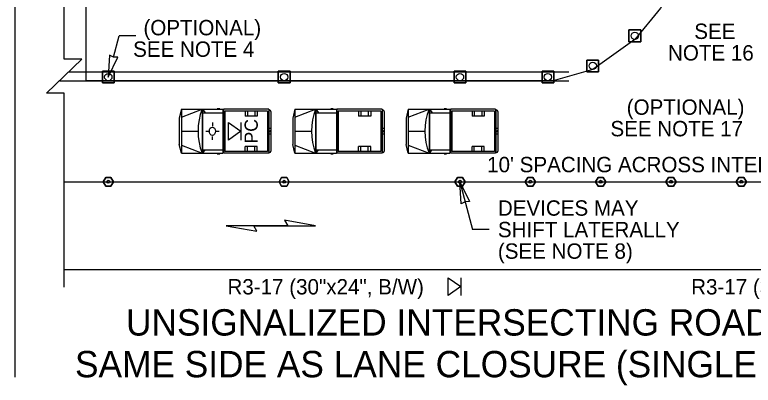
# Model space of a CAD drawing. Extents: x 99999.1 to 100095.7, y 99995 to 100010.7.
# Drawn here: x 100065.25 to 100068.61, y 100001.65 to 100003.336 of the extents above; entities that cross this region are included whole.
import ezdxf

# ---------------------------------------------------------------- set-up
doc = ezdxf.new("R2010")
doc.units = 0
for name, color, linetype in [('RD_ED_ShoulderPavedEdge', 7, 'Continuous'), ('RD_MK_LineDblYellowCenter', 7, 'Continuous'), ('RD_MK_LineEdgeWhite', 7, 'Continuous'), ('SH_DE_DetailHeading2Text', 7, 'Continuous'), ('TR_WZ_MotoristVehicle', 7, 'Continuous'), ('TR_WZ_PortableSignMountBlk-Wht', 7, 'Continuous'), ('TR_WZ_TrafficCone', 7, 'Continuous'), ('TR_WZ_TubularMarker', 7, 'Continuous'), ('TR_WZ_WorkZoneDetails', 7, 'Continuous'), ('TR_WZ_WorkZoneTextCurrent', 7, 'Continuous')]:
    doc.layers.add(name, color=color, linetype=linetype)

msp = doc.modelspace()

# ---------------------------------------------------------------- linework, layer by layer
at = {"layer": 'RD_ED_ShoulderPavedEdge'}
msp.add_line((100065.475, 100002.1759), (100070.275, 100002.1759), dxfattribs=at)
at = {"layer": 'RD_MK_LineDblYellowCenter'}
for p, q in [((100065.4957, 100003.0759), (100067.7712, 100003.0759)), ((100065.4543, 100003.0359), (100067.7712, 100003.0359))]:
    msp.add_line(p, q, dxfattribs=at)
at = {"layer": 'RD_MK_LineEdgeWhite'}
msp.add_line((100065.475, 100002.5759), (100070.275, 100002.5759), dxfattribs=at)
at = {"layer": 'TR_WZ_MotoristVehicle'}
for p, q in [((100066.008, 100002.9059), (100065.9987, 100002.8655)), ((100066.008, 100002.9059), (100066.008, 100002.7059)), ((100066.008, 100002.9059), (100066.1969, 100002.9059)), ((100066.008, 100002.8693), (100066.1025, 100002.9059)), ((100066.1025, 100002.9059), (100066.1025, 100002.7059)), ((100066.1042, 100002.9059), (100066.1042, 100002.7059)), ((100066.1042, 100002.9059), (100066.1162, 100002.8904)), ((100066.1042, 100002.8904), (100066.1969, 100002.8904)), ((100066.1712, 100002.9087), (100066.1825, 100002.9087)), ((100066.1969, 100002.9059), (100066.1969, 100002.7059)), ((100066.4054, 100002.9059), (100066.1997, 100002.9059)), ((100066.1997, 100002.9059), (100066.1997, 100002.7059)), ((100066.3995, 100002.8979), (100066.2055, 100002.8979)), ((100066.2055, 100002.8979), (100066.2055, 100002.7139)), ((100066.2982, 100002.8979), (100066.2982, 100002.8749)), ((100066.3082, 100002.8979), (100066.3082, 100002.8749)), ((100066.3422, 100002.8979), (100066.3422, 100002.8749)), ((100066.3532, 100002.8979), (100066.3532, 100002.8749)), ((100066.3995, 100002.8979), (100066.3995, 100002.7139)), ((100066.4054, 100002.9059), (100066.4054, 100002.7059)), ((100066.4105, 100002.9026), (100066.4061, 100002.9026)), ((100066.4061, 100002.9026), (100066.4061, 100002.7092)), ((100066.415, 100002.8965), (100066.415, 100002.7153)), ((100066.5243, 100002.9059), (100066.515, 100002.8655)), ((100066.5243, 100002.9059), (100066.5243, 100002.7059)), ((100066.5243, 100002.9059), (100066.7132, 100002.9059)), ((100066.5243, 100002.8693), (100066.6187, 100002.9059)), ((100066.6187, 100002.9059), (100066.6187, 100002.7059)), ((100066.6204, 100002.9059), (100066.6204, 100002.7059)), ((100066.6204, 100002.9059), (100066.6325, 100002.8904)), ((100066.6204, 100002.8904), (100066.7132, 100002.8904)), ((100066.6874, 100002.9087), (100066.6987, 100002.9087)), ((100066.7132, 100002.9059), (100066.7132, 100002.7059)), ((100066.9216, 100002.9059), (100066.7159, 100002.9059)), ((100066.7159, 100002.9059), (100066.7159, 100002.7059)), ((100066.9158, 100002.8979), (100066.7218, 100002.8979)), ((100066.7218, 100002.8979), (100066.7218, 100002.7139)), ((100066.8145, 100002.8979), (100066.8145, 100002.8749)), ((100066.8244, 100002.8979), (100066.8244, 100002.8749)), ((100066.8585, 100002.8979), (100066.8585, 100002.8749)), ((100066.8694, 100002.8979), (100066.8694, 100002.8749)), ((100066.9158, 100002.8979), (100066.9158, 100002.7139)), ((100066.9216, 100002.9059), (100066.9216, 100002.7059)), ((100066.9268, 100002.9026), (100066.9223, 100002.9026)), ((100066.9223, 100002.9026), (100066.9223, 100002.7092)), ((100066.9313, 100002.8965), (100066.9313, 100002.7153)), ((100067.0405, 100002.9059), (100067.0313, 100002.8655)), ((100067.0405, 100002.9059), (100067.0405, 100002.7059)), ((100067.0405, 100002.9059), (100067.2294, 100002.9059)), ((100067.0405, 100002.8693), (100067.135, 100002.9059)), ((100067.135, 100002.9059), (100067.135, 100002.7059)), ((100067.1367, 100002.9059), (100067.1367, 100002.7059)), ((100067.1367, 100002.9059), (100067.1487, 100002.8904)), ((100067.1367, 100002.8904), (100067.2294, 100002.8904)), ((100067.2037, 100002.9087), (100067.215, 100002.9087)), ((100067.2294, 100002.9059), (100067.2294, 100002.7059)), ((100067.4379, 100002.9059), (100067.2322, 100002.9059)), ((100067.2322, 100002.9059), (100067.2322, 100002.7059)), ((100067.4321, 100002.8979), (100067.238, 100002.8979)), ((100067.238, 100002.8979), (100067.238, 100002.7139)), ((100067.3308, 100002.8979), (100067.3308, 100002.8749)), ((100067.3407, 100002.8979), (100067.3407, 100002.8749)), ((100067.3747, 100002.8979), (100067.3747, 100002.8749)), ((100067.3857, 100002.8979), (100067.3857, 100002.8749)), ((100067.4321, 100002.8979), (100067.4321, 100002.7139)), ((100067.4379, 100002.9059), (100067.4379, 100002.7059)), ((100067.4431, 100002.9026), (100067.4386, 100002.9026)), ((100067.4386, 100002.9026), (100067.4386, 100002.7092)), ((100067.4475, 100002.8965), (100067.4475, 100002.7153)), ((100065.9987, 100002.8655), (100065.9987, 100002.7463)), ((100066.3532, 100002.8749), (100066.2982, 100002.8749)), ((100066.515, 100002.8655), (100066.515, 100002.7463)), ((100066.8694, 100002.8749), (100066.8145, 100002.8749)), ((100067.0313, 100002.8655), (100067.0313, 100002.7463)), ((100067.3857, 100002.8749), (100067.3308, 100002.8749)), ((100066.1495, 100002.8455), (100066.1495, 100002.8294)), ((100066.415, 100002.82), (100066.4061, 100002.8162)), ((100066.9313, 100002.82), (100066.9223, 100002.8162)), ((100067.4475, 100002.82), (100067.4386, 100002.8162)), ((100066.008, 100002.8059), (100066.0839, 100002.8059)), ((100066.1194, 100002.806), (100066.132, 100002.806)), ((100066.1636, 100002.8056), (100066.1636, 100002.8056)), ((100066.1804, 100002.8051), (100066.1655, 100002.8055)), ((100066.415, 100002.7918), (100066.4061, 100002.7956)), ((100066.4126, 100002.8059), (100066.4085, 100002.8059)), ((100066.4105, 100002.8087), (100066.4105, 100002.8031)), ((100066.5243, 100002.8059), (100066.6002, 100002.8059)), ((100066.9313, 100002.7918), (100066.9223, 100002.7956)), ((100066.9289, 100002.8059), (100066.9247, 100002.8059)), ((100066.9268, 100002.8087), (100066.9268, 100002.8031)), ((100067.0405, 100002.8059), (100067.1164, 100002.8059)), ((100067.4475, 100002.7918), (100067.4386, 100002.7956)), ((100067.4451, 100002.8059), (100067.441, 100002.8059)), ((100067.4431, 100002.8087), (100067.4431, 100002.8031)), ((100066.1502, 100002.7674), (100066.1499, 100002.7825)), ((100066.008, 100002.7059), (100065.9987, 100002.7463)), ((100066.008, 100002.7425), (100066.1025, 100002.7059)), ((100066.1042, 100002.7214), (100066.1969, 100002.7214)), ((100066.1141, 100002.7214), (100066.1042, 100002.7059)), ((100066.2982, 100002.7139), (100066.2982, 100002.7369)), ((100066.3532, 100002.7369), (100066.2982, 100002.7369)), ((100066.3082, 100002.7139), (100066.3082, 100002.7369)), ((100066.3422, 100002.7139), (100066.3422, 100002.7369)), ((100066.3532, 100002.7139), (100066.3532, 100002.7369)), ((100066.5243, 100002.7059), (100066.515, 100002.7463)), ((100066.5243, 100002.7425), (100066.6187, 100002.7059)), ((100066.6204, 100002.7214), (100066.7132, 100002.7214)), ((100066.6304, 100002.7214), (100066.6204, 100002.7059)), ((100066.8145, 100002.7139), (100066.8145, 100002.7369)), ((100066.8694, 100002.7369), (100066.8145, 100002.7369)), ((100066.8244, 100002.7139), (100066.8244, 100002.7369)), ((100066.8585, 100002.7139), (100066.8585, 100002.7369)), ((100066.8694, 100002.7139), (100066.8694, 100002.7369)), ((100067.0405, 100002.7059), (100067.0313, 100002.7463)), ((100067.0405, 100002.7425), (100067.135, 100002.7059)), ((100067.1367, 100002.7214), (100067.2294, 100002.7214)), ((100067.1467, 100002.7214), (100067.1367, 100002.7059)), ((100067.3308, 100002.7139), (100067.3308, 100002.7369)), ((100067.3857, 100002.7369), (100067.3308, 100002.7369)), ((100067.3407, 100002.7139), (100067.3407, 100002.7369)), ((100067.3747, 100002.7139), (100067.3747, 100002.7369)), ((100067.3857, 100002.7139), (100067.3857, 100002.7369)), ((100066.008, 100002.7059), (100066.1969, 100002.7059)), ((100066.1712, 100002.7031), (100066.1825, 100002.7031)), ((100066.4054, 100002.7059), (100066.1997, 100002.7059)), ((100066.3995, 100002.7139), (100066.2055, 100002.7139)), ((100066.4105, 100002.7092), (100066.4061, 100002.7092)), ((100066.5243, 100002.7059), (100066.7132, 100002.7059)), ((100066.6874, 100002.7031), (100066.6987, 100002.7031)), ((100066.9216, 100002.7059), (100066.7159, 100002.7059)), ((100066.9158, 100002.7139), (100066.7218, 100002.7139)), ((100066.9268, 100002.7092), (100066.9223, 100002.7092)), ((100067.0405, 100002.7059), (100067.2294, 100002.7059)), ((100067.2037, 100002.7031), (100067.215, 100002.7031)), ((100067.4379, 100002.7059), (100067.2322, 100002.7059)), ((100067.4321, 100002.7139), (100067.238, 100002.7139)), ((100067.4431, 100002.7092), (100067.4386, 100002.7092))]:
    msp.add_line(p, q, dxfattribs=at)
for centre, major_axis, start_param, end_param in [((100066.2374, 100002.8059), (0, -0.2099), 4.215667, 5.208926), ((100066.4105, 100002.8965), (0, 0.0061), 4.712389, 6.283185), ((100066.7537, 100002.8059), (0, -0.2099), 4.215667, 5.208926), ((100066.9268, 100002.8965), (0, 0.0061), 4.712389, 6.283185), ((100067.27, 100002.8059), (0, -0.2099), 4.215667, 5.208926), ((100067.4431, 100002.8965), (0, 0.0061), 4.712389, 6.283185), ((100066.4105, 100002.7153), (0, -0.0061), 0, 1.570796), ((100066.9268, 100002.7153), (0, -0.0061), 0, 1.570796), ((100067.4431, 100002.7153), (0, -0.0061), 0, 1.570796)]:
    msp.add_ellipse(centre, major_axis=major_axis, ratio=0.73155, start_param=start_param, end_param=end_param, dxfattribs=at)
for centre, major_axis in [((100066.1495, 100002.8059), (0, 0.0193)), ((100066.4105, 100002.8059), (0, 0.00282)), ((100066.9268, 100002.8059), (0, 0.00282)), ((100067.4431, 100002.8059), (0, 0.00282))]:
    msp.add_ellipse(centre, major_axis=major_axis, ratio=0.73155, dxfattribs=at)
at = {"layer": 'TR_WZ_PortableSignMountBlk-Wht'}
for p, q in [((100066.2793, 100002.8458), (100066.2793, 100002.7658)), ((100067.279, 100002.1389), (100067.279, 100002.0589))]:
    msp.add_line(p, q, dxfattribs=at)
for points in [[(100066.2793, 100002.8059), (100066.2219, 100002.7658), (100066.2219, 100002.8458)], [(100067.279, 100002.0989), (100067.2215, 100002.0589), (100067.2215, 100002.1389)]]:
    msp.add_lwpolyline(points, close=True, dxfattribs=at)
at = {"layer": 'TR_WZ_TrafficCone'}
for points in [[(100068.0447, 100003.267), (100068.0981, 100003.267), (100068.0981, 100003.2136), (100068.0447, 100003.2136), (100068.0447, 100003.267)], [(100068.0447, 100003.2136), (100068.0981, 100003.2136), (100068.0981, 100003.267), (100068.0447, 100003.267), (100068.0447, 100003.2136)], [(100067.853, 100003.1302), (100067.9064, 100003.1302), (100067.9064, 100003.0768), (100067.853, 100003.0768), (100067.853, 100003.1302)], [(100067.853, 100003.0768), (100067.9064, 100003.0768), (100067.9064, 100003.1302), (100067.853, 100003.1302), (100067.853, 100003.0768)], [(100065.649, 100003.0792), (100065.7024, 100003.0792), (100065.7024, 100003.0259), (100065.649, 100003.0259), (100065.649, 100003.0792)], [(100065.649, 100003.0259), (100065.7024, 100003.0259), (100065.7024, 100003.0792), (100065.649, 100003.0792), (100065.649, 100003.0259)], [(100066.449, 100003.0792), (100066.5024, 100003.0792), (100066.5024, 100003.0259), (100066.449, 100003.0259), (100066.449, 100003.0792)], [(100066.449, 100003.0259), (100066.5024, 100003.0259), (100066.5024, 100003.0792), (100066.449, 100003.0792), (100066.449, 100003.0259)], [(100067.249, 100003.0792), (100067.3024, 100003.0792), (100067.3024, 100003.0259), (100067.249, 100003.0259), (100067.249, 100003.0792)], [(100067.249, 100003.0259), (100067.3024, 100003.0259), (100067.3024, 100003.0792), (100067.249, 100003.0792), (100067.249, 100003.0259)], [(100067.649, 100003.0792), (100067.7024, 100003.0792), (100067.7024, 100003.0259), (100067.649, 100003.0259), (100067.649, 100003.0792)], [(100067.649, 100003.0259), (100067.7024, 100003.0259), (100067.7024, 100003.0792), (100067.649, 100003.0792), (100067.649, 100003.0259)]]:
    msp.add_lwpolyline(points, dxfattribs=at)
for centre in [(100068.0714, 100003.2403), (100067.8797, 100003.1035), (100065.6757, 100003.0526), (100066.4757, 100003.0526), (100067.2757, 100003.0526), (100067.6757, 100003.0526)]:
    msp.add_circle(centre, 0.0167, dxfattribs=at)
at = {"layer": 'TR_WZ_TubularMarker'}
for points in [[(100065.6526, 100002.5759), (100065.6641, 100002.5959), (100065.6872, 100002.5959), (100065.6988, 100002.5759), (100065.6872, 100002.5559), (100065.6641, 100002.5559)], [(100066.4526, 100002.5759), (100066.4641, 100002.5959), (100066.4872, 100002.5959), (100066.4988, 100002.5759), (100066.4872, 100002.5559), (100066.4641, 100002.5559)], [(100067.2526, 100002.5759), (100067.2641, 100002.5959), (100067.2872, 100002.5959), (100067.2988, 100002.5759), (100067.2872, 100002.5559), (100067.2641, 100002.5559)], [(100067.5726, 100002.5759), (100067.5841, 100002.5959), (100067.6072, 100002.5959), (100067.6188, 100002.5759), (100067.6072, 100002.5559), (100067.5841, 100002.5559)], [(100067.8926, 100002.5759), (100067.9041, 100002.5959), (100067.9272, 100002.5959), (100067.9388, 100002.5759), (100067.9272, 100002.5559), (100067.9041, 100002.5559)], [(100068.2126, 100002.5759), (100068.2241, 100002.5959), (100068.2472, 100002.5959), (100068.2588, 100002.5759), (100068.2472, 100002.5559), (100068.2241, 100002.5559)], [(100068.5326, 100002.5759), (100068.5441, 100002.5959), (100068.5672, 100002.5959), (100068.5788, 100002.5759), (100068.5672, 100002.5559), (100068.5441, 100002.5559)]]:
    msp.add_lwpolyline(points, close=True, dxfattribs=at)
for points in [[(100065.6641, 100002.5559), (100065.6872, 100002.5559), (100065.6988, 100002.5759), (100065.6872, 100002.5959), (100065.6641, 100002.5959), (100065.6526, 100002.5759), (100065.6641, 100002.5559)], [(100066.4641, 100002.5559), (100066.4872, 100002.5559), (100066.4988, 100002.5759), (100066.4872, 100002.5959), (100066.4641, 100002.5959), (100066.4526, 100002.5759), (100066.4641, 100002.5559)], [(100067.2641, 100002.5559), (100067.2872, 100002.5559), (100067.2988, 100002.5759), (100067.2872, 100002.5959), (100067.2641, 100002.5959), (100067.2526, 100002.5759), (100067.2641, 100002.5559)], [(100067.5841, 100002.5559), (100067.6072, 100002.5559), (100067.6188, 100002.5759), (100067.6072, 100002.5959), (100067.5841, 100002.5959), (100067.5726, 100002.5759), (100067.5841, 100002.5559)], [(100067.9041, 100002.5559), (100067.9272, 100002.5559), (100067.9388, 100002.5759), (100067.9272, 100002.5959), (100067.9041, 100002.5959), (100067.8926, 100002.5759), (100067.9041, 100002.5559)], [(100068.2241, 100002.5559), (100068.2472, 100002.5559), (100068.2588, 100002.5759), (100068.2472, 100002.5959), (100068.2241, 100002.5959), (100068.2126, 100002.5759), (100068.2241, 100002.5559)], [(100068.5441, 100002.5559), (100068.5672, 100002.5559), (100068.5788, 100002.5759), (100068.5672, 100002.5959), (100068.5441, 100002.5959), (100068.5326, 100002.5759), (100068.5441, 100002.5559)]]:
    msp.add_lwpolyline(points, dxfattribs=at)
for centre in [(100065.6757, 100002.5759), (100066.4757, 100002.5759), (100067.2757, 100002.5759), (100067.5957, 100002.5759), (100067.9157, 100002.5759), (100068.2357, 100002.5759), (100068.5557, 100002.5759)]:
    msp.add_circle(centre, 0.00667, dxfattribs=at)
at = {"layer": 'TR_WZ_WorkZoneDetails'}
for p, q in [((100065.25, 100010.275), (100065.25, 100001.6859)), ((100065.6993, 100003.1433), (100065.7245, 100003.2406)), ((100065.8007, 100003.2406), (100065.7245, 100003.2406)), ((100067.2757, 100002.5759), (100067.3321, 100002.3584)), ((100066.4922, 100002.3759), (100066.3378, 100002.3759)), ((100066.3378, 100002.3759), (100066.4922, 100002.3759)), ((100067.4083, 100002.3584), (100067.3321, 100002.3584))]:
    msp.add_line(p, q, dxfattribs=at)
msp.add_lwpolyline([(100065.475, 100002.0959), (100065.475, 100002.9785), (100065.395, 100002.9785), (100065.555, 100003.1333), (100065.475, 100003.1333), (100065.475, 100004.0159)], dxfattribs=at)
for points in [[(100068.3383, 100003.9359), (100068.3383, 100003.7126), (100068.264, 100003.5159), (100068.1883, 100003.3659), (100068.1883, 100003.3659), (100068.1883, 100003.3659), (100068.0714, 100003.2236), (100068.0714, 100003.2236), (100068.0714, 100003.2236), (100067.8797, 100003.0868), (100067.699, 100003.0359), (100066.499, 100003.0359), (100065.699, 100003.0359), (100065.575, 100003.0359), (100065.575, 100003.9359)], [(100065.6757, 100003.0526), (100065.719, 100003.1429), (100065.6992, 100003.1433), (100065.6817, 100003.1525)], [(100067.2757, 100002.5759), (100067.319, 100002.4856), (100067.2992, 100002.4852), (100067.2816, 100002.4759)], [(100066.6179, 100002.3759), (100066.4779, 100002.4006), (100066.4922, 100002.3759)], [(100066.2121, 100002.3759), (100066.3521, 100002.3512), (100066.3378, 100002.3759)]]:
    msp.add_lwpolyline(points, close=True, dxfattribs=at)

# ---------------------------------------------------------------- texts
at = {"layer": 'SH_DE_DetailHeading2Text'}
for s, p in [('UNSIGNALIZED INTERSECTING ROADWAY DETAIL', (100065.7563, 100001.8759)), ('SAME SIDE AS LANE CLOSURE (SINGLE OPEN LANE)', (100065.524, 100001.6859))]:
    msp.add_text(s, height=0.12, rotation=360, dxfattribs=at).set_placement(p)
at = {"layer": 'TR_WZ_MotoristVehicle'}
msp.add_text('PC', height=0.06, rotation=90, dxfattribs=at).set_placement((100066.3557, 100002.7499))
at = {"layer": 'TR_WZ_WorkZoneDetails'}
for p in [(100066.2179, 100002.063), (100068.3277, 100002.0629)]:
    msp.add_text('R3-17 (30"x24", B/W)', height=0.07, rotation=360, dxfattribs=at).set_placement(p)
at = {"layer": 'TR_WZ_WorkZoneTextCurrent'}
for s, p in [('(OPTIONAL)', (100065.8355, 100003.2426)), ('SEE', (100068.3418, 100003.2259)), ('SEE NOTE 4', (100065.7886, 100003.1446)), ('NOTE 16', (100068.2223, 100003.1279)), ('(OPTIONAL)', (100068.0344, 100002.8808)), ('SEE NOTE 17', (100067.9603, 100002.7828)), ("10' SPACING ACROSS INTERSECTION", (100067.3993, 100002.6192)), ('DEVICES MAY', (100067.4483, 100002.4214)), ('SHIFT LATERALLY', (100067.4483, 100002.3234)), ('(SEE NOTE 8)', (100067.4483, 100002.2254))]:
    msp.add_text(s, height=0.07, dxfattribs=at).set_placement(p)

doc.saveas('drawing.dxf')
